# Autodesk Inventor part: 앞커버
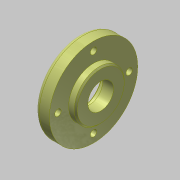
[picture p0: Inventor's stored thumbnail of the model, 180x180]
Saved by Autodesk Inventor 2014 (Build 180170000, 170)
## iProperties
Created: 2015-12
Part Number: 앞커버
Document SubType Name: Modeling
Designer: mdu
Density: 2.71 g/cm^3
Material: 알루미늄 6061
Mass: 70.9323 g
Surface Area: 93.9278 cm^2
Volume: 26.1743 cm^3
Appearance: 널링 45
Author: mdu
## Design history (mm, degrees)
sketch "스케치1"
  geometry: L1 (-7.5, 0)-(7.5, 0); L2 (-7.5, 0)-(-7.5, 31); L3 (-7.5, 31)-(2.5, 31); L4 (2.5, 31)-(2.5, 17.5); L5 (2.5, 17.5)-(7.5, 17.5); L6 (7.5, 17.5)-(7.5, 0); 2 further points
  constraints: 12 end point, 3 perpendicular, 1 coincident, 1 horizontal, 1 midpoint, 1 parallel
  dimensions: "d0" = 15 distance of L1.start L1.end; "d1" = 62 diameter of L3 L1; "d2" = 35 diameter of L5 L1; "d5" = 10 distance of L2.end L3.end
revolve "회전1" sketch "스케치1" stored, may be unused: angle "d6" = 90 deg
sketch "스케치2" dims "d42" = 50
  geometry: 3 further points
  constraints: 2 vertical alignment, 1 coincident, 2 other
hole "구멍1" sketch "스케치2" at (0, 25) diameter "d8" = 4.5; stored, may be unused: countersink angle "d12" = 90 deg, drill point angle "d14" = 118 deg; dims "d9" = 6, "d10" = 8, "d11" = 4.4, "d13" = 8
hole "구멍2" diameter "d20" = 18; stored, may be unused: countersink angle "d24" = 90 deg, drill point angle "d26" = 0 deg; dims "d18" = 10, "d19" = 10, "d21" = 6, "d22" = 8, "d23" = 4.4, "d25" = 8
hole "구멍3" diameter "d34" = 30; stored, may be unused: countersink angle "d38" = 90 deg, drill point angle "d40" = 0 deg; dims "d32" = 10, "d33" = 10, "d35" = 6, "d36" = 4, "d37" = 2, "d39" = 7.3
fillet "모깎기1" dims "d27" = 3, "d41" = 0.3
chamfer "모따기1" distance "d29" = 1; stored, may be unused: second distance "d30" = 2, angle "d31" = 45 deg
node "솔리드1"
pattern_circular "원형 패턴1" dims angle "d16" = 360 deg
